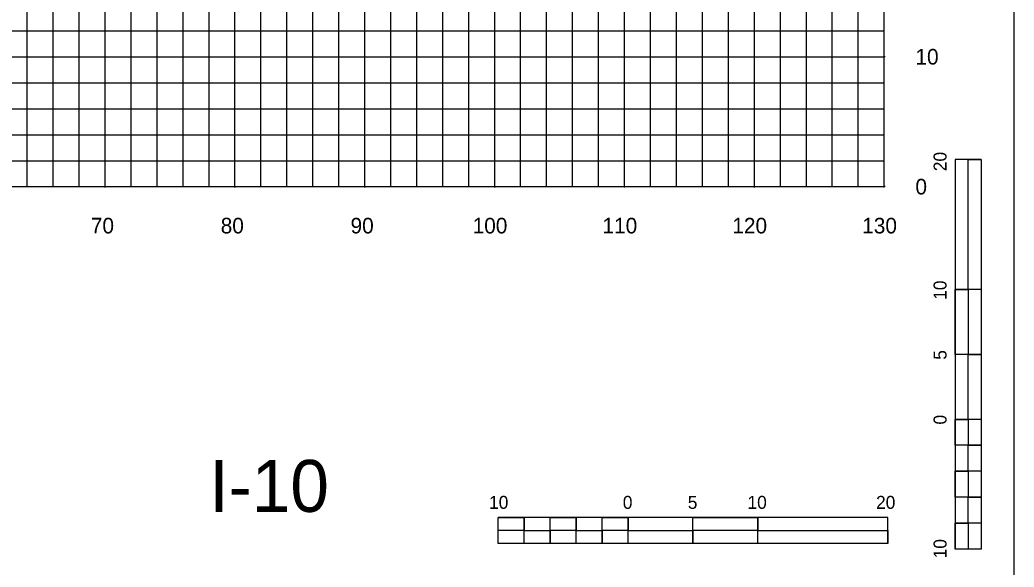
# Model space of a CAD drawing. Extents: x 1797809 to 2198143, y 249608 to 1237864.
# Drawn here: x 2194956.3 to 2195032.9, y 1237228.8 to 1237270.9 of the extents above; entities that cross this region are included whole.
import ezdxf

# ---------------------------------------------------------------- set-up
doc = ezdxf.new("R2010")
doc.units = 0
for name, color, linetype in [('10', 7, 'Continuous'), ('29', 7, 'Continuous'), ('3', 7, 'Continuous'), ('31', 7, 'Continuous'), ('60', 7, 'Continuous'), ('GSSHT', 7, 'Continuous'), ('Level 33', 7, 'Continuous')]:
    doc.layers.add(name, color=color, linetype=linetype)

msp = doc.modelspace()

# ---------------------------------------------------------------- linework, layer by layer
at = {"layer": '29'}
for p, q in [((2195028.332, 1237260.195), (2195028.332, 1237230.195)), ((2195030.332, 1237260.195), (2195028.332, 1237260.195)), ((2195028.332, 1237260.195), (2195028.332, 1237230.195)), ((2195030.332, 1237260.195), (2195028.332, 1237260.195)), ((2195030.332, 1237260.195), (2195030.332, 1237250.195)), ((2195030.332, 1237260.195), (2195030.332, 1237230.195)), ((2195030.332, 1237260.195), (2195030.332, 1237250.195)), ((2195030.332, 1237260.195), (2195030.332, 1237230.195)), ((2195029.332, 1237250.195), (2195028.332, 1237250.195)), ((2195030.332, 1237250.195), (2195028.332, 1237250.195)), ((2195029.332, 1237250.195), (2195028.332, 1237250.195)), ((2195030.332, 1237250.195), (2195028.332, 1237250.195)), ((2195029.332, 1237250.195), (2195029.332, 1237245.195)), ((2195029.332, 1237250.195), (2195029.332, 1237245.195)), ((2195030.332, 1237245.195), (2195028.332, 1237245.195)), ((2195030.332, 1237245.195), (2195028.332, 1237245.195)), ((2195030.332, 1237245.195), (2195029.332, 1237245.195)), ((2195030.332, 1237245.195), (2195029.332, 1237245.195)), ((2195030.332, 1237245.195), (2195030.332, 1237240.195)), ((2195030.332, 1237245.195), (2195030.332, 1237240.195)), ((2195029.332, 1237240.195), (2195028.332, 1237240.195)), ((2195030.332, 1237240.195), (2195028.332, 1237240.195)), ((2195029.332, 1237240.195), (2195028.332, 1237240.195)), ((2195030.332, 1237240.195), (2195028.332, 1237240.195)), ((2195029.332, 1237240.195), (2195029.332, 1237238.195)), ((2195029.332, 1237240.195), (2195029.332, 1237238.195)), ((2195030.332, 1237238.195), (2195029.332, 1237238.195)), ((2195030.332, 1237238.195), (2195029.332, 1237238.195)), ((2195030.332, 1237238.195), (2195030.332, 1237236.195)), ((2195030.332, 1237238.195), (2195030.332, 1237236.195)), ((2195029.332, 1237236.195), (2195028.332, 1237236.195)), ((2195029.332, 1237236.195), (2195028.332, 1237236.195)), ((2195029.332, 1237236.195), (2195029.332, 1237234.195)), ((2195029.332, 1237236.195), (2195029.332, 1237234.195)), ((2195030.332, 1237234.195), (2195029.332, 1237234.195)), ((2195030.332, 1237234.195), (2195029.332, 1237234.195)), ((2195030.332, 1237234.195), (2195030.332, 1237232.195)), ((2195030.332, 1237234.195), (2195030.332, 1237232.195)), ((2195023.128, 1237232.63), (2194993.128, 1237232.63)), ((2194993.128, 1237230.63), (2194993.128, 1237232.63)), ((2195023.128, 1237232.63), (2194993.128, 1237232.63)), ((2194993.128, 1237230.63), (2194993.128, 1237232.63)), ((2194995.128, 1237231.63), (2194995.128, 1237232.63)), ((2194995.128, 1237231.63), (2194995.128, 1237232.63)), ((2194999.128, 1237231.63), (2194999.128, 1237232.63)), ((2194999.128, 1237231.63), (2194999.128, 1237232.63)), ((2195003.128, 1237231.63), (2195003.128, 1237232.63)), ((2195003.128, 1237230.63), (2195003.128, 1237232.63)), ((2195003.128, 1237231.63), (2195003.128, 1237232.63)), ((2195003.128, 1237230.63), (2195003.128, 1237232.63)), ((2195008.128, 1237230.63), (2195008.128, 1237232.63)), ((2195008.128, 1237230.63), (2195008.128, 1237232.63)), ((2195013.128, 1237231.63), (2195013.128, 1237232.63)), ((2195013.128, 1237230.63), (2195013.128, 1237232.63)), ((2195013.128, 1237231.63), (2195013.128, 1237232.63)), ((2195013.128, 1237230.63), (2195013.128, 1237232.63)), ((2195023.128, 1237230.63), (2195023.128, 1237232.63)), ((2195023.128, 1237230.63), (2195023.128, 1237232.63)), ((2194995.128, 1237231.63), (2194993.128, 1237231.63)), ((2194995.128, 1237231.63), (2194993.128, 1237231.63)), ((2194997.128, 1237230.63), (2194997.128, 1237231.63)), ((2194999.128, 1237231.63), (2194997.128, 1237231.63)), ((2194997.128, 1237230.63), (2194997.128, 1237231.63)), ((2194999.128, 1237231.63), (2194997.128, 1237231.63)), ((2195001.128, 1237230.63), (2195001.128, 1237231.63)), ((2195003.128, 1237231.63), (2195001.128, 1237231.63)), ((2195001.128, 1237230.63), (2195001.128, 1237231.63)), ((2195003.128, 1237231.63), (2195001.128, 1237231.63)), ((2195008.128, 1237230.63), (2195008.128, 1237231.63)), ((2195013.128, 1237231.63), (2195008.128, 1237231.63)), ((2195008.128, 1237230.63), (2195008.128, 1237231.63)), ((2195013.128, 1237231.63), (2195008.128, 1237231.63)), ((2195029.332, 1237232.195), (2195028.332, 1237232.195)), ((2195029.332, 1237232.195), (2195028.332, 1237232.195)), ((2195029.332, 1237232.195), (2195029.332, 1237230.195)), ((2195029.332, 1237232.195), (2195029.332, 1237230.195)), ((2195023.128, 1237230.63), (2194993.128, 1237230.63)), ((2195023.128, 1237230.63), (2194993.128, 1237230.63)), ((2194997.128, 1237230.63), (2194995.128, 1237230.63)), ((2194997.128, 1237230.63), (2194995.128, 1237230.63)), ((2195001.128, 1237230.63), (2194999.128, 1237230.63)), ((2195001.128, 1237230.63), (2194999.128, 1237230.63)), ((2195008.128, 1237230.63), (2195003.128, 1237230.63)), ((2195008.128, 1237230.63), (2195003.128, 1237230.63)), ((2195023.128, 1237230.63), (2195013.128, 1237230.63)), ((2195023.128, 1237230.63), (2195013.128, 1237230.63)), ((2195030.332, 1237230.195), (2195028.332, 1237230.195)), ((2195030.332, 1237230.195), (2195028.332, 1237230.195))]:
    msp.add_line(p, q, dxfattribs=at)
for points in [[(2195029.332, 1237250.195), (2195029.332, 1237260.195), (2195030.332, 1237260.195), (2195030.332, 1237250.195)], [(2195029.332, 1237250.195), (2195029.332, 1237260.195), (2195030.332, 1237260.195), (2195030.332, 1237250.195)], [(2195028.332, 1237245.195), (2195028.332, 1237250.195), (2195029.332, 1237250.195), (2195029.332, 1237245.195)], [(2195028.332, 1237245.195), (2195028.332, 1237250.195), (2195029.332, 1237250.195), (2195029.332, 1237245.195)], [(2195029.332, 1237240.195), (2195029.332, 1237245.195), (2195030.332, 1237245.195), (2195030.332, 1237240.195)], [(2195029.332, 1237240.195), (2195029.332, 1237245.195), (2195030.332, 1237245.195), (2195030.332, 1237240.195)], [(2195028.332, 1237238.195), (2195028.332, 1237240.195), (2195029.332, 1237240.195), (2195029.332, 1237238.195)], [(2195028.332, 1237238.195), (2195028.332, 1237240.195), (2195029.332, 1237240.195), (2195029.332, 1237238.195)], [(2195029.332, 1237236.195), (2195029.332, 1237238.195), (2195030.332, 1237238.195), (2195030.332, 1237236.195)], [(2195029.332, 1237236.195), (2195029.332, 1237238.195), (2195030.332, 1237238.195), (2195030.332, 1237236.195)], [(2195028.332, 1237234.195), (2195028.332, 1237236.195), (2195029.332, 1237236.195), (2195029.332, 1237234.195)], [(2195028.332, 1237234.195), (2195028.332, 1237236.195), (2195029.332, 1237236.195), (2195029.332, 1237234.195)], [(2195029.332, 1237232.195), (2195029.332, 1237234.195), (2195030.332, 1237234.195), (2195030.332, 1237232.195)], [(2195029.332, 1237232.195), (2195029.332, 1237234.195), (2195030.332, 1237234.195), (2195030.332, 1237232.195)], [(2194993.128, 1237232.63), (2194995.128, 1237232.63), (2194995.128, 1237231.63), (2194993.128, 1237231.63)], [(2194993.128, 1237232.63), (2194995.128, 1237232.63), (2194995.128, 1237231.63), (2194993.128, 1237231.63)], [(2194997.128, 1237232.63), (2194999.128, 1237232.63), (2194999.128, 1237231.63), (2194997.128, 1237231.63)], [(2194997.128, 1237232.63), (2194999.128, 1237232.63), (2194999.128, 1237231.63), (2194997.128, 1237231.63)], [(2195001.128, 1237232.63), (2195003.128, 1237232.63), (2195003.128, 1237231.63), (2195001.128, 1237231.63)], [(2195001.128, 1237232.63), (2195003.128, 1237232.63), (2195003.128, 1237231.63), (2195001.128, 1237231.63)], [(2195008.128, 1237232.63), (2195013.128, 1237232.63), (2195013.128, 1237231.63), (2195008.128, 1237231.63)], [(2195008.128, 1237232.63), (2195013.128, 1237232.63), (2195013.128, 1237231.63), (2195008.128, 1237231.63)], [(2194995.128, 1237231.63), (2194997.128, 1237231.63), (2194997.128, 1237230.63), (2194995.128, 1237230.63)], [(2194995.128, 1237231.63), (2194997.128, 1237231.63), (2194997.128, 1237230.63), (2194995.128, 1237230.63)], [(2194999.128, 1237231.63), (2195001.128, 1237231.63), (2195001.128, 1237230.63), (2194999.128, 1237230.63)], [(2194999.128, 1237231.63), (2195001.128, 1237231.63), (2195001.128, 1237230.63), (2194999.128, 1237230.63)], [(2195003.128, 1237231.63), (2195008.128, 1237231.63), (2195008.128, 1237230.63), (2195003.128, 1237230.63)], [(2195003.128, 1237231.63), (2195008.128, 1237231.63), (2195008.128, 1237230.63), (2195003.128, 1237230.63)], [(2195013.128, 1237231.63), (2195023.128, 1237231.63), (2195023.128, 1237230.63), (2195013.128, 1237230.63)], [(2195013.128, 1237231.63), (2195023.128, 1237231.63), (2195023.128, 1237230.63), (2195013.128, 1237230.63)], [(2195028.332, 1237230.195), (2195028.332, 1237232.195), (2195029.332, 1237232.195), (2195029.332, 1237230.195)], [(2195028.332, 1237230.195), (2195028.332, 1237232.195), (2195029.332, 1237232.195), (2195029.332, 1237230.195)]]:
    msp.add_lwpolyline(points, close=True, dxfattribs=at)
at = {"layer": '3'}
msp.add_line((2195032.86, 1237228.046), (2195032.86, 1237323.046), dxfattribs=at)
at = {"layer": '60'}
for p, q in [((2195022.86, 1237258.106), (2195022.86, 1237318.106)), ((2195022.92, 1237268.106), (2195022.86, 1237268.106)), ((2194892.86, 1237258.106), (2195022.86, 1237258.106)), ((2194962.86, 1237258.046), (2194962.86, 1237258.106)), ((2194972.86, 1237258.046), (2194972.86, 1237258.106)), ((2194982.86, 1237258.046), (2194982.86, 1237258.106)), ((2194992.86, 1237258.046), (2194992.86, 1237258.106)), ((2195002.86, 1237258.046), (2195002.86, 1237258.106)), ((2195012.86, 1237258.046), (2195012.86, 1237258.106)), ((2195022.86, 1237258.046), (2195022.86, 1237258.106)), ((2195022.92, 1237258.106), (2195022.86, 1237258.106))]:
    msp.add_line(p, q, dxfattribs=at)
at = {"layer": 'GSSHT'}
for p, q in [((2194956.86, 1237258.106), (2194956.86, 1237318.106)), ((2194958.86, 1237258.106), (2194958.86, 1237318.106)), ((2194960.86, 1237258.106), (2194960.86, 1237318.106)), ((2194962.86, 1237258.106), (2194962.86, 1237318.106)), ((2194964.86, 1237258.106), (2194964.86, 1237318.106)), ((2194966.86, 1237258.106), (2194966.86, 1237318.106)), ((2194968.86, 1237258.106), (2194968.86, 1237318.106)), ((2194970.86, 1237258.106), (2194970.86, 1237318.106)), ((2194972.86, 1237258.106), (2194972.86, 1237318.106)), ((2194974.86, 1237258.106), (2194974.86, 1237318.106)), ((2194976.86, 1237258.106), (2194976.86, 1237318.106)), ((2194978.86, 1237258.106), (2194978.86, 1237318.106)), ((2194980.86, 1237258.106), (2194980.86, 1237318.106)), ((2194982.86, 1237258.106), (2194982.86, 1237318.106)), ((2194984.86, 1237258.106), (2194984.86, 1237318.106)), ((2194986.86, 1237258.106), (2194986.86, 1237318.106)), ((2194988.86, 1237258.106), (2194988.86, 1237318.106)), ((2194990.86, 1237258.106), (2194990.86, 1237318.106)), ((2194992.86, 1237258.106), (2194992.86, 1237318.106)), ((2194994.86, 1237258.106), (2194994.86, 1237318.106)), ((2194996.86, 1237258.106), (2194996.86, 1237318.106)), ((2194998.86, 1237258.106), (2194998.86, 1237318.106)), ((2195000.86, 1237258.106), (2195000.86, 1237318.106)), ((2195002.86, 1237258.106), (2195002.86, 1237318.106)), ((2195004.86, 1237258.106), (2195004.86, 1237318.106)), ((2195006.86, 1237258.106), (2195006.86, 1237318.106)), ((2195008.86, 1237258.106), (2195008.86, 1237318.106)), ((2195010.86, 1237258.106), (2195010.86, 1237318.106)), ((2195012.86, 1237258.106), (2195012.86, 1237318.106)), ((2195014.86, 1237258.106), (2195014.86, 1237318.106)), ((2195016.86, 1237258.106), (2195016.86, 1237318.106)), ((2195018.86, 1237258.106), (2195018.86, 1237318.106)), ((2195020.86, 1237258.106), (2195020.86, 1237318.106)), ((2195022.86, 1237258.106), (2195022.86, 1237318.106)), ((2194892.86, 1237270.106), (2195022.86, 1237270.106)), ((2194892.86, 1237268.106), (2195022.86, 1237268.106)), ((2194892.86, 1237266.106), (2195022.86, 1237266.106)), ((2194892.86, 1237264.106), (2195022.86, 1237264.106)), ((2194892.86, 1237262.106), (2195022.86, 1237262.106)), ((2194892.86, 1237260.106), (2195022.86, 1237260.106)), ((2194892.86, 1237258.106), (2195022.86, 1237258.106))]:
    msp.add_line(p, q, dxfattribs=at)

# ---------------------------------------------------------------- texts
at = {"layer": '10'}
for s, p in [('70', (2194961.76, 1237254.506)), ('80', (2194971.76, 1237254.506)), ('90', (2194981.76, 1237254.506)), ('100', (2194991.16, 1237254.506)), ('110', (2195001.16, 1237254.506)), ('120', (2195011.16, 1237254.506)), ('130', (2195021.16, 1237254.506))]:
    msp.add_text(s, height=1.2, dxfattribs=at).set_placement(p)
at = {"layer": '29'}
for s, height, rotation, p in [('20', 0.9991, 90.0572, (2195027.658, 1237259.295)), ('20', 0.9991, 90.0572, (2195027.658, 1237259.295)), ('10', 0.9991, 90.0572, (2195027.658, 1237249.395)), ('10', 0.9991, 90.0572, (2195027.658, 1237249.395)), ('5', 1, 90.0572, (2195027.658, 1237244.78)), ('5', 1, 90.0572, (2195027.658, 1237244.78)), ('0', 1, 90.0572, (2195027.658, 1237239.795)), ('0', 1, 90.0572, (2195027.658, 1237239.795)), ('10', 0.9991, 0.0572, (2194992.428, 1237233.305)), ('10', 0.9991, 0.0572, (2194992.428, 1237233.305)), ('0', 1, 0.0572, (2195002.728, 1237233.304)), ('0', 1, 0.0572, (2195002.728, 1237233.304)), ('5', 0.999, 0.0572, (2195007.729, 1237233.304)), ('5', 0.999, 0.0572, (2195007.729, 1237233.304)), ('10', 0.9991, 0.0572, (2195012.328, 1237233.305)), ('10', 0.9991, 0.0572, (2195012.328, 1237233.305)), ('20', 0.9991, 0.0572, (2195022.229, 1237233.305)), ('20', 0.9991, 0.0572, (2195022.229, 1237233.305)), ('10', 0.9991, 90.0572, (2195027.658, 1237229.495)), ('10', 0.9991, 90.0572, (2195027.658, 1237229.495))]:
    msp.add_text(s, height=height, rotation=rotation, dxfattribs=at).set_placement(p)
at = {"layer": '31'}
for s, p in [('10', (2195025.26, 1237267.506)), ('0', (2195025.26, 1237257.506))]:
    msp.add_text(s, height=1.2, dxfattribs=at).set_placement(p)
at = {"layer": 'Level 33'}
msp.add_text('I-10', height=3.9977, rotation=360, dxfattribs=at).set_placement((2194970.885, 1237233.073))

doc.saveas('drawing.dxf')
